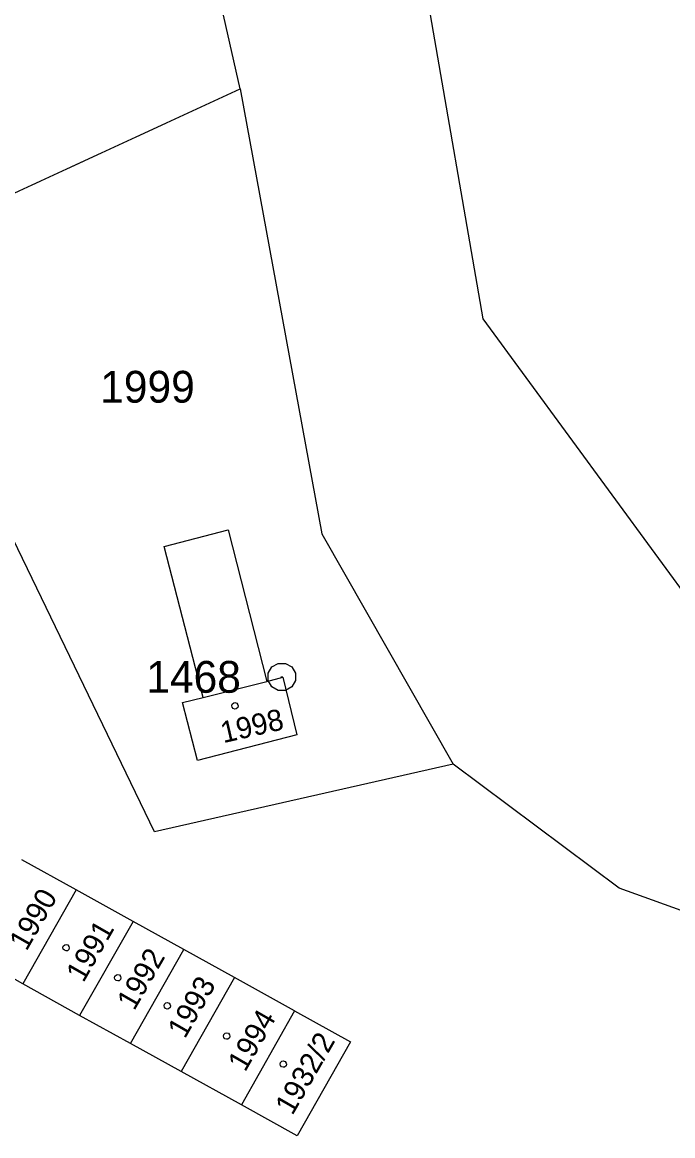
# Model space of a CAD drawing. Extents: x -528274 to -527531, y -1079304 to -1078580.
# Drawn here: x -527898.8 to -527864, y -1078698 to -1078638.4 of the extents above; entities that cross this region are included whole.
import ezdxf

# ---------------------------------------------------------------- set-up
doc = ezdxf.new("R2010")
doc.units = 0
doc.layers.add('katastrální mapa', color=7, linetype='Continuous')

msp = doc.modelspace()

# ---------------------------------------------------------------- linework, layer by layer
at = {"layer": 'katastrální mapa'}
for p, q in [((-527887.13, -1078641.97), (-527896.74, -1078598.85)), ((-527877.4, -1078635.45), (-527874.15, -1078654.27)), ((-527906.56, -1078650.93), (-527887.13, -1078641.97)), ((-527887.13, -1078641.97), (-527882.75, -1078665.76)), ((-527874.15, -1078654.27), (-527858.07, -1078676.23)), ((-527891.7, -1078681.71), (-527899.51, -1078665.53)), ((-527891.19, -1078666.45), (-527887.77, -1078665.56)), ((-527887.77, -1078665.56), (-527885.69, -1078673.66)), ((-527882.75, -1078665.76), (-527875.73, -1078678.1)), ((-527889.1, -1078674.52), (-527891.19, -1078666.45)), ((-527889.1, -1078674.52), (-527885.69, -1078673.66)), ((-527885.69, -1078673.66), (-527884.84, -1078673.44)), ((-527884.94, -1078673.42), (-527884.84, -1078673.42)), ((-527884.84, -1078673.44), (-527884.1, -1078676.53)), ((-527890.2, -1078674.8), (-527889.1, -1078674.52)), ((-527889.4, -1078677.9), (-527890.2, -1078674.8)), ((-527884.1, -1078676.53), (-527889.4, -1078677.9)), ((-527875.73, -1078678.1), (-527891.7, -1078681.71)), ((-527866.85, -1078684.72), (-527875.73, -1078678.1)), ((-527895.89, -1078684.82), (-527898.8, -1078683.21)), ((-527895.89, -1078684.82), (-527898.75, -1078689.84)), ((-527892.85, -1078686.5), (-527895.89, -1078684.82)), ((-527856.97, -1078688.3), (-527866.85, -1078684.72)), ((-527892.85, -1078686.5), (-527895.71, -1078691.53)), ((-527890.14, -1078688.01), (-527892.85, -1078686.5)), ((-527892.99, -1078693.03), (-527890.14, -1078688.01)), ((-527887.43, -1078689.51), (-527890.14, -1078688.01)), ((-527898.75, -1078689.84), (-527901.65, -1078688.23)), ((-527895.71, -1078691.53), (-527898.75, -1078689.84)), ((-527887.43, -1078689.51), (-527890.28, -1078694.53)), ((-527884.22, -1078691.29), (-527887.43, -1078689.51)), ((-527892.99, -1078693.03), (-527895.71, -1078691.53)), ((-527884.22, -1078691.29), (-527887.06, -1078696.31)), ((-527884.22, -1078691.29), (-527881.23, -1078692.95)), ((-527881.23, -1078692.95), (-527884.07, -1078697.97)), ((-527890.28, -1078694.53), (-527892.99, -1078693.03)), ((-527887.06, -1078696.31), (-527890.28, -1078694.53)), ((-527884.07, -1078697.97), (-527887.06, -1078696.31))]:
    msp.add_line(p, q, dxfattribs=at)
for points in [[(-527884.7, -1078672.7), (-527884.36, -1078672.89), (-527884.17, -1078673.23), (-527884.17, -1078673.62), (-527884.36, -1078673.96), (-527884.7, -1078674.15), (-527885.09, -1078674.15), (-527885.43, -1078673.96), (-527885.62, -1078673.62), (-527885.62, -1078673.23), (-527885.43, -1078672.89), (-527885.09, -1078672.7)], [(-527887.4, -1078674.8), (-527887.3, -1078674.82), (-527887.25, -1078674.91), (-527887.23, -1078674.97), (-527887.25, -1078675.06), (-527887.33, -1078675.13), (-527887.4, -1078675.14), (-527887.49, -1078675.11), (-527887.55, -1078675.05), (-527887.57, -1078674.97), (-527887.55, -1078674.88), (-527887.47, -1078674.81)], [(-527896.43, -1078687.74), (-527896.33, -1078687.76), (-527896.28, -1078687.85), (-527896.26, -1078687.91), (-527896.28, -1078688), (-527896.36, -1078688.07), (-527896.43, -1078688.08), (-527896.52, -1078688.05), (-527896.58, -1078687.99), (-527896.6, -1078687.91), (-527896.58, -1078687.82), (-527896.5, -1078687.75)], [(-527893.67, -1078689.35), (-527893.57, -1078689.37), (-527893.52, -1078689.46), (-527893.5, -1078689.52), (-527893.52, -1078689.61), (-527893.6, -1078689.68), (-527893.67, -1078689.69), (-527893.76, -1078689.66), (-527893.82, -1078689.6), (-527893.84, -1078689.52), (-527893.82, -1078689.43), (-527893.74, -1078689.36)], [(-527891.02, -1078690.85), (-527890.92, -1078690.87), (-527890.87, -1078690.96), (-527890.85, -1078691.02), (-527890.87, -1078691.11), (-527890.95, -1078691.18), (-527891.02, -1078691.19), (-527891.11, -1078691.16), (-527891.17, -1078691.1), (-527891.19, -1078691.02), (-527891.17, -1078690.93), (-527891.09, -1078690.86)], [(-527887.85, -1078692.47), (-527887.75, -1078692.49), (-527887.7, -1078692.58), (-527887.68, -1078692.64), (-527887.7, -1078692.73), (-527887.78, -1078692.8), (-527887.85, -1078692.81), (-527887.94, -1078692.78), (-527888, -1078692.72), (-527888.02, -1078692.64), (-527888, -1078692.55), (-527887.92, -1078692.48)], [(-527884.82, -1078693.97), (-527884.72, -1078693.99), (-527884.67, -1078694.08), (-527884.65, -1078694.14), (-527884.67, -1078694.23), (-527884.75, -1078694.3), (-527884.82, -1078694.31), (-527884.91, -1078694.28), (-527884.97, -1078694.22), (-527884.99, -1078694.14), (-527884.97, -1078694.05), (-527884.89, -1078693.98)]]:
    msp.add_lwpolyline(points, close=True, dxfattribs=at)

# ---------------------------------------------------------------- texts
for s, p in [('1999', (-527894.607, -1078658.75)), ('1468', (-527892.142, -1078674.27))]:
    msp.add_text(s, height=1.7, dxfattribs=at).set_placement(p)
for s, rotation, p in [('1998', 12.94885, (-527888.023, -1078676.971)), ('1990', 60.16057, (-527898.549, -1078688.132)), ('1991', 60.16057, (-527895.509, -1078689.822)), ('1992', 60.16057, (-527892.789, -1078691.322)), ('1993', 60.16057, (-527890.079, -1078692.822)), ('1994', 60.16057, (-527886.859, -1078694.602)), ('1932/2', 60.16057, (-527884.329, -1078696.922))]:
    msp.add_text(s, height=1.14, rotation=rotation, dxfattribs=at).set_placement(p)

doc.saveas('drawing.dxf')
